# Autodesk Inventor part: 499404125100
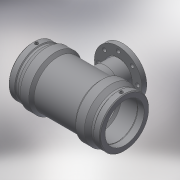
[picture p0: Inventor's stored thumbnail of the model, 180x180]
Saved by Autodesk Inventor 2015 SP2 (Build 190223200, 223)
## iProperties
Created: 2017-06
Part Number: 499404125100
Material: Generic
Description: PLASSON FLANGED TEE 125x100x125
Document SubType Name: Modeling
Designer: KIM
Mass: 57.3761 g
Surface Area: 241.06 cm^2
Volume: 57.3761 cm^3
Density: 1 g/cm^3
Appearance: Default
Author: KIM
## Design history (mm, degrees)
derived "499404.ipt"
feature "Solid1::499404.ipt"
tag "TaggingFeature1"
body "Solid1"
other parameters: "d13" = 382, "d14" = 17.6296, "d17" = 112.5, "d18" = 125, "d19" = 3.52592, "d20" = 168 deg, "d22" = 153.45, "d23" = 165, "d24" = 148.8465, "d25" = 135 deg, "d26" = 267.4, "d27" = 135 deg, "d29" = 88, "d35" = 15, "d39" = 5 deg, "d45" = 4, "d46" = 14, "d47" = 0, "d55" = 148.5, "d56" = 165, "d57" = 133.7, "d58" = 135 deg, "d59" = 86, "d60" = 86, "d61" = 135 deg, "d72" = 173.81, "d73" = 86.905, "d87" = 158, "d90" = 125, "d91" = 15 deg, "d93" = 22, "d95" = 4.74, "d97" = 18, "d100" = 0, "d102" = 360 deg, "d105" = 0, "d107" = 0, "d108" = 3, "d109" = 0, "d110" = 25.8, "d111" = 8.6, "d_" = 125, "L_" = 382, "L_1" = 86, "D_" = 165, "A_" = 88, "d_2" = 12, "t_" = 22, "d_1" = 158, "s_" = 18
